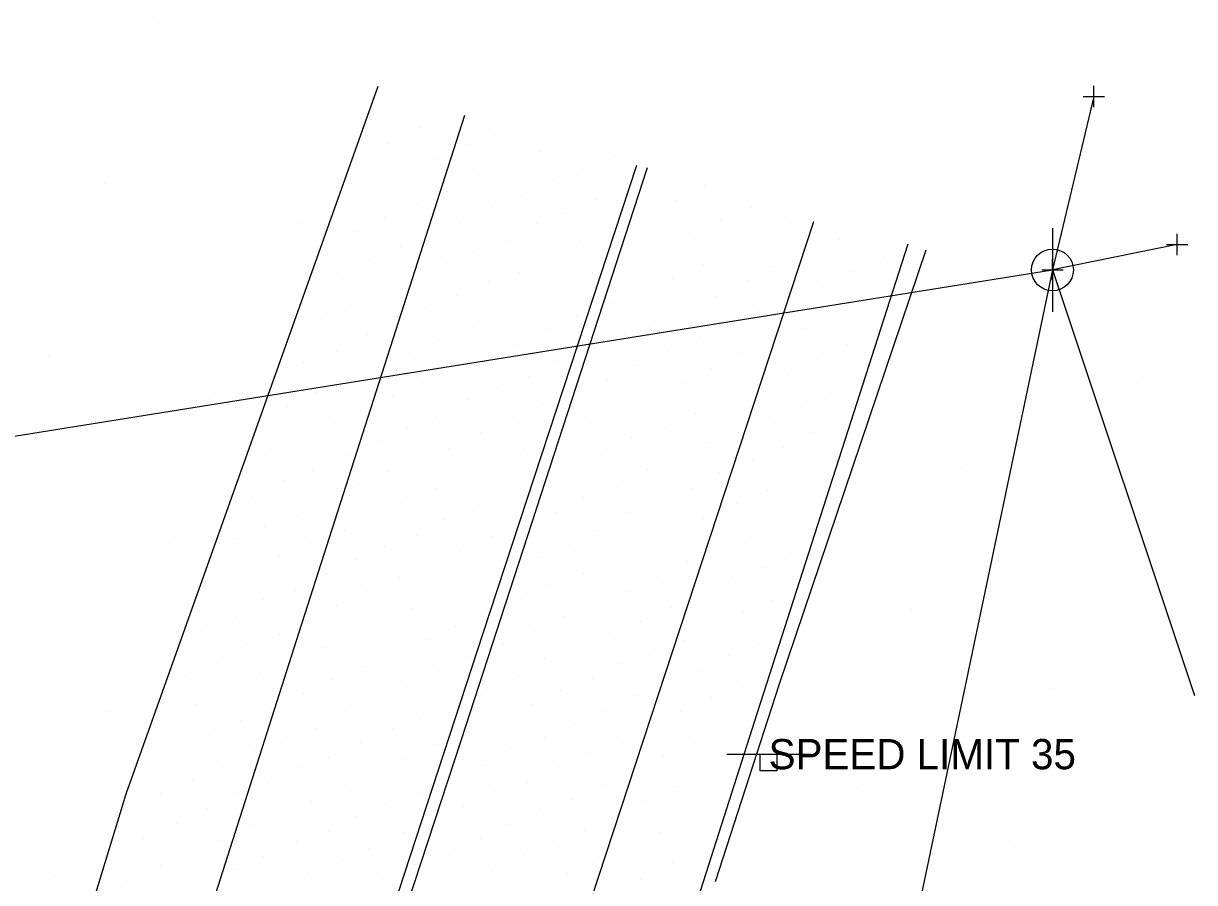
# Model space of a CAD drawing. Extents: x 0 to 1739264, y 0 to 465304.
# Drawn here: x 1739010.3 to 1739080.1, y 465244.9 to 465296.2 of the extents above; entities that cross this region are included whole.
import ezdxf

# ---------------------------------------------------------------- set-up
doc = ezdxf.new("R2010")
doc.units = 0
for name, color, linetype in [('Default', 7, 'Continuous'), ('S_Ground_SpotElevation', 7, 'Continuous'), ('S_Survey_Shot', 7, 'Continuous'), ('S_Terrain_Holes', 7, 'Continuous'), ('S_Terrain_Imported_Contours', 7, 'Continuous'), ('S_Terrain_Triangle_Vertices', 7, 'Continuous'), ('S_Text', 7, 'Continuous'), ('S_Traffic_Sign_SinglePost', 7, 'Continuous'), ('S_Utilities_AG_Communications', 7, 'Continuous'), ('S_Utilities_GuyWire3', 7, 'Continuous'), ('S_Utilities_Pole_Power', 7, 'Continuous')]:
    doc.layers.add(name, color=color, linetype=linetype)

# ---------------------------------------------------------------- blocks, each defined once
blk = doc.blocks.new('POINT_DISPLAY')
at = {"layer": 'Default'}
blk.add_line((0, 0), (0, 0), dxfattribs=at)

msp = doc.modelspace()

# ---------------------------------------------------------------- linework, layer by layer
at = {"layer": 'S_Survey_Shot'}
for p, q in [((1739074.096331, 465291.168485), (1739074.093669, 465292.440915)), ((1739073.458785, 465291.803369), (1739074.731215, 465291.806031)), ((1739074.095, 465291.8047), (1739074.095, 465291.8047)), ((1739079.068331, 465282.334085), (1739079.065669, 465283.606515)), ((1739078.430785, 465282.968969), (1739079.703215, 465282.971631)), ((1739079.067, 465282.9703), (1739079.067, 465282.9703)), ((1739071.634331, 465280.822185), (1739071.631669, 465282.094615)), ((1739071.634331, 465280.822185), (1739071.631669, 465282.094615)), ((1739070.996785, 465281.457069), (1739072.269215, 465281.459731)), ((1739070.996785, 465281.457069), (1739072.269215, 465281.459731)), ((1739071.633, 465281.4584), (1739071.633, 465281.4584)), ((1739071.633, 465281.4584), (1739071.633, 465281.4584))]:
    msp.add_line(p, q, dxfattribs=at)
at = {"layer": 'S_Terrain_Holes'}
for points in [[(1738856.840841, 464753.154236), (1738864.057181, 464775.7454), (1738868.5654, 464789.017493), (1738877.2832, 464816.667503), (1738894.6762, 464871.298499), (1738908.615099, 464914.227276), (1738925.968706, 464967.700787), (1738931.720797, 464985.987408), (1738937.417894, 465002.810894), (1738942.679705, 465019.271282), (1738946.949205, 465031.543377), (1738957.801699, 465065.627422), (1738970.933794, 465105.251873), (1738981.084093, 465138.214092), (1738987.350398, 465160.501376), (1738994.117907, 465180.316815), (1739002.701601, 465206.97459), (1739010.434099, 465230.699413), (1739016.388903, 465250.214703), (1739024.141405, 465271.975903), (1739031.418001, 465292.412487)], [(1739063.0161, 465283.000195), (1739054.024202, 465255.054608), (1739049.4284, 465240.685009), (1739049.815203, 465236.204296), (1739047.1234, 465227.914501), (1739043.67, 465216.427685), (1739042.442102, 465214.161694), (1739040.084001, 465206.821911), (1739030.010698, 465174.744122), (1739023.975405, 465156.789227), (1739021.450701, 465151.395123), (1739017.4265, 465140.617291), (1739011.494493, 465124.187481)]]:
    msp.add_lwpolyline(points, dxfattribs=at)
at = {"layer": 'S_Terrain_Imported_Contours'}
for points in [[(1739036.578798, 465290.667492), (1739026.541399, 465259.332012), (1739013.6942, 465219.063488), (1738999.442797, 465174.850323), (1738985.582293, 465132.024273), (1738970.199999, 465085.108929), (1738952.192003, 465029.358624), (1738937.750505, 464984.645672), (1738924.644899, 464943.318829), (1738905.560399, 464884.157001), (1738885.695701, 464823.240203), (1738863.6675, 464755.019294), (1738861.917132, 464749.554455)], [(1738871.099421, 464743.042961), (1738872.2397, 464746.6146), (1738884.148, 464784.717796), (1738894.996801, 464817.751098), (1738911.848199, 464869.926002), (1738930.302797, 464927.737591), (1738944.359194, 464971.624127), (1738958.087007, 465014.085796), (1738974.263903, 465064.602886), (1738992.370806, 465120.419476), (1739017.617296, 465198.443401), (1739037.679499, 465259.797009), (1739046.847902, 465287.700512)], [(1739047.457499, 465287.543713), (1739036.361299, 465253.386303), (1739023.629793, 465214.581799), (1739012.533693, 465180.659283), (1739000.839403, 465144.457989), (1738988.796495, 465107.402325), (1738973.524599, 465060.372296), (1738959.218599, 465015.277325), (1738946.4993, 464976.09959), (1738932.162996, 464931.360577), (1738918.509, 464889.008399), (1738909.080301, 464859.274802), (1738899.9057, 464830.791198), (1738886.617, 464789.705497), (1738873.9013, 464749.930595), (1738871.579396, 464742.691331)], [(1738880.224773, 464736.284008), (1738881.2288, 464739.449607), (1738893.811099, 464778.771506), (1738907.7459, 464822.0036), (1738924.2609, 464872.5013), (1738939.901598, 464921.282574), (1738960.695803, 464986.497418), (1738980.188906, 465046.965923), (1739002.893496, 465116.574383), (1739021.976305, 465176.353375), (1739041.488497, 465235.866894), (1739057.407396, 465284.356213)]]:
    msp.add_lwpolyline(points, dxfattribs=at)
at = {"layer": 'S_Terrain_Triangle_Vertices'}
msp.add_lwpolyline([(1739051.533602, 465244.994091), (1739055.348597, 465256.783306), (1739064.1029, 465282.664288)], dxfattribs=at)
at = {"layer": 'S_Traffic_Sign_SinglePost'}
msp.add_line((1739052.210924, 465252.5851), (1739057.201076, 465252.5851), dxfattribs=at)
msp.add_lwpolyline([(1739054.206985, 465252.5851), (1739055.205015, 465252.5851), (1739055.205015, 465251.58707), (1739054.206985, 465251.58707)], close=True, dxfattribs=at)
at = {"layer": 'S_Utilities_AG_Communications'}
for p, q in [((1738988.171694, 465268.093792), (1739071.632502, 465281.458386)), ((1739071.632502, 465281.458386), (1739080.108797, 465256.089306))]:
    msp.add_line(p, q, dxfattribs=at)
msp.add_lwpolyline([(1739071.632502, 465281.458386), (1739041.748697, 465139.054608), (1739010.442507, 464998.221295)], dxfattribs=at)
at = {"layer": 'S_Utilities_GuyWire3'}
for points in [[(1739074.095, 465291.8047), (1739071.633, 465281.4584)], [(1739079.067, 465282.9703), (1739071.633, 465281.4584)]]:
    msp.add_lwpolyline(points, dxfattribs=at)
at = {"layer": 'S_Utilities_Pole_Power'}
msp.add_line((1739071.633, 465283.953476), (1739071.633, 465278.963324), dxfattribs=at)
msp.add_circle((1739071.633, 465281.4584), 1.247538, dxfattribs=at)

# ---------------------------------------------------------------- block references
at = {"layer": 'S_Ground_SpotElevation'}
for p in [(1739018.331897, 465296.158886), (1739029.631404, 465292.058697), (1739033.025096, 465291.630669), (1739035.831004, 465290.67205), (1739033.931895, 465289.929375), (1739038.329997, 465289.616508), (1739032.058299, 465288.971733), (1739036.66151, 465288.954643), (1739041.016093, 465288.540947), (1739034.966289, 465288.082451), (1739039.135387, 465287.766411), (1739045.516887, 465288.302299), (1739032.908305, 465287.334038), (1739037.410991, 465287.123833), (1739043.579784, 465287.524956), (1739048.260905, 465287.169731), (1739015.122502, 465286.585491), (1739031.047008, 465286.474663), (1739041.871684, 465286.863335), (1739046.316295, 465286.642143), (1739050.909404, 465286.47979), (1739035.533885, 465286.132866), (1739039.940807, 465285.921318), (1739044.387096, 465285.669243), (1739049.167094, 465285.623344), (1739033.797191, 465285.412163), (1739038.212505, 465285.292656), (1739053.671611, 465285.191093), (1739026.848696, 465284.261303), (1739031.823588, 465284.55645), (1739036.323711, 465284.325249), (1739040.844005, 465284.206474), (1739042.583507, 465284.809135), (1739047.330791, 465284.614189), (1739051.849406, 465284.413628), (1739056.03831, 465284.321098), (1739030.015605, 465283.742607), (1739034.422191, 465283.477348), (1739045.295787, 465283.968559), (1739049.995311, 465283.687553), (1739054.47639, 465283.530815), (1739032.725108, 465282.850151), (1739039.057384, 465283.150566), (1739043.491893, 465283.109428), (1739048.208598, 465282.860649), (1739058.932689, 465283.263603), (1739030.914683, 465282.081474), (1739037.111888, 465282.523003), (1739041.536082, 465282.186455), (1739046.353984, 465282.06768), (1739052.625987, 465282.538628), (1739057.001689, 465282.439751), (1739061.552409, 465282.141899), (1739035.492198, 465281.829155), (1739050.803294, 465281.774223), (1739055.002483, 465281.683037), (1739059.759898, 465281.370415), (1739028.999004, 465281.19915), (1739033.495891, 465281.005669), (1739037.979503, 465280.789238), (1739039.851909, 465281.314384), (1739044.208903, 465281.301933), (1739048.983195, 465280.968925), (1739053.469585, 465280.828544), (1739031.606395, 465280.10894), (1739042.446605, 465280.590874), (1739047.168285, 465280.190849), (1739057.89619, 465280.43914), (1739029.800487, 465279.37896), (1739036.087199, 465279.937797), (1739040.656901, 465279.708916), (1739045.278606, 465279.530571), (1739049.717998, 465279.332451), (1739051.5955, 465279.86663), (1739055.961711, 465279.795708), (1739060.554393, 465279.503593), (1739034.240001, 465279.16375), (1739038.740794, 465278.843193), (1739043.269298, 465278.65435), (1739054.099986, 465279.10125), (1739058.733287, 465278.738823), (1739069.336102, 465279.151196), (1739028.072215, 465278.512749), (1739032.451488, 465278.278618), (1739037.115489, 465278.116142), (1739041.441783, 465277.916923), (1739047.897502, 465278.391533), (1739052.426402, 465278.163261), (1739056.902385, 465277.952934), (1739030.808208, 465277.580742), (1739035.040385, 465277.325127), (1739046.101298, 465277.635795), (1739050.611705, 465277.352714), (1739054.863811, 465277.217216), (1739028.914409, 465276.621635), (1739033.269786, 465276.551689), (1739039.578899, 465276.949394), (1739044.302898, 465276.770439), (1739048.701884, 465276.714653), (1739059.386302, 465277.008842), (1739011.746905, 465276.385601), (1739026.963206, 465275.967338), (1739037.756602, 465276.165947), (1739042.103801, 465275.98748), (1739052.9304, 465276.458794), (1739057.63679, 465276.145805), (1739031.413097, 465275.611381), (1739035.868907, 465275.521538), (1739040.368785, 465275.102592), (1739046.891185, 465275.744194), (1739051.315196, 465275.590996), (1739055.889293, 465275.285454), (1739029.575206, 465274.908134), (1739034.05601, 465274.730522), (1739038.555705, 465274.465874), (1739045.099193, 465274.877983), (1739049.560008, 465274.727836), (1739054.031108, 465274.540947), (1739076.705701, 465274.790814), (1739021.371295, 465273.739086), (1739027.76649, 465274.135307), (1739032.306407, 465273.943535), (1739036.833507, 465273.741875), (1739043.136088, 465274.237846), (1739047.743388, 465273.957207), (1739052.061412, 465273.768486), (1739058.388286, 465274.08477), (1739025.9976, 465273.305961), (1739030.355083, 465273.019829), (1739041.227611, 465273.469047), (1739045.897502, 465272.989921), (1739056.658305, 465273.395805), (1739034.873393, 465272.618339), (1739039.467784, 465272.60186), (1739044.101909, 465272.285576), (1739050.322703, 465272.920341), (1739054.751292, 465272.710503), (1739028.817699, 465272.279838), (1739033.145305, 465271.97686), (1739037.522899, 465271.750908), (1739048.565684, 465272.009453), (1739052.9304, 465271.789848), (1739057.407512, 465271.780083), (1739026.760997, 465271.526298), (1739031.423289, 465271.203667), (1739041.9882, 465271.529961), (1739046.542094, 465271.449638), (1739051.154796, 465271.193046), (1739025.028697, 465270.729545), (1739029.529796, 465270.441337), (1739035.605998, 465270.8377), (1739040.107005, 465270.686455), (1739044.726604, 465270.496757), (1739055.575694, 465270.856987), (1739027.504314, 465269.488579), (1739033.898601, 465270.183403), (1739038.261912, 465269.979423), (1739043.025005, 465269.601738), (1739047.511699, 465269.56353), (1739049.297191, 465270.18267), (1739053.72581, 465270.095268), (1739066.196399, 465269.595592), (1739025.828288, 465268.900566), (1739032.015605, 465269.440239), (1739036.673991, 465269.220634), (1739041.132609, 465268.887138), (1739051.791911, 465269.40374), (1739056.378307, 465269.141533), (1739030.222301, 465268.671562), (1739034.887187, 465268.40081), (1739039.229411, 465268.236626), (1739045.672008, 465268.633842), (1739050.13911, 465268.445976), (1739054.621806, 465268.298759), (1739023.863505, 465267.813774), (1739028.561595, 465267.7929), (1739032.813701, 465267.597465), (1739043.681895, 465267.881523), (1739048.194011, 465267.585136), (1739052.77589, 465267.503715), (1739026.620494, 465266.794975), (1739031.071483, 465266.74395), (1739037.398387, 465267.357963), (1739042.051799, 465267.01226), (1739046.429484, 465266.968681), (1739024.672588, 465266.18206), (1739035.40269, 465266.555839), (1739040.220897, 465266.179863), (1739050.820293, 465266.638359), (1739055.442088, 465266.354423), (1739022.881908, 465265.435478), (1739029.388591, 465265.896049), (1739033.723308, 465265.644585), (1739038.201182, 465265.570854), (1739044.477702, 465265.904961), (1739049.086284, 465265.796806), (1739053.617198, 465265.535087), (1739073.571, 465265.408093), (1739019.005694, 465265.219311), (1739027.365306, 465265.120415), (1739031.809001, 465264.995659), (1739036.294505, 465264.781425), (1739042.823405, 465265.099052), (1739047.256389, 465264.826836), (1739051.681102, 465264.820244), (1739056.022807, 465264.634575), (1739025.531413, 465264.350639), (1739030.063213, 465264.171562), (1739034.410411, 465263.910942), (1739041.005199, 465264.297661), (1739045.356883, 465264.069511), (1739049.889384, 465264.074272), (1739023.970897, 465263.450249), (1739028.360911, 465263.345146), (1739038.819804, 465263.642876), (1739043.645305, 465263.353325), (1739054.345012, 465263.687675), (1739022.027415, 465262.653007), (1739032.67039, 465263.110039), (1739037.174297, 465262.938042), (1739041.617992, 465262.617851), (1739048.099803, 465263.082085), (1739052.491496, 465263.051811), (1739026.506602, 465262.364433), (1739030.726512, 465262.256157), (1739035.281596, 465261.989067), (1739039.985088, 465261.833305), (1739046.230785, 465262.273735), (1739050.658092, 465261.955742), (1739024.555614, 465261.80352), (1739028.909312, 465261.473442), (1739033.448985, 465261.295952), (1739037.8968, 465261.128593), (1739044.349101, 465261.510307), (1739048.904582, 465261.33184), (1739054.941692, 465261.75164), (1739063.2186, 465261.191601), (1739022.88499, 465260.690605), (1739027.078593, 465260.515312), (1739031.53651, 465260.416313), (1739042.535106, 465260.796196), (1739047.072093, 465260.512627), (1739053.223094, 465261.078056), (1739020.910503, 465259.870048), (1739025.545116, 465259.732841), (1739036.030498, 465260.203056), (1739040.767589, 465259.982963), (1739045.232707, 465259.745537), (1739051.509196, 465260.406547), (1739023.586314, 465259.168266), (1739029.69099, 465259.653984), (1739034.276805, 465259.412651), (1739038.916209, 465259.203544), (1739049.685496, 465259.377861), (1739054.080791, 465259.210136), (1739028.095012, 465258.936333), (1739032.429484, 465258.71624), (1739036.862804, 465258.342705), (1739043.4145, 465259.006157), (1739047.886485, 465258.766411), (1739052.311992, 465258.481743), (1739021.856914, 465258.080498), (1739026.090404, 465258.072563), (1739030.493205, 465257.808281), (1739035.017192, 465257.649101), (1739041.332683, 465258.262749), (1739045.908488, 465257.991142), (1739019.957988, 465257.209892), (1739024.349803, 465257.332939), (1739028.693309, 465257.04644), (1739039.768291, 465257.248466), (1739044.224712, 465257.067436), (1739050.527507, 465257.591972), (1739022.349193, 465256.262749), (1739026.944499, 465256.225273), (1739033.113383, 465256.679619), (1739037.861186, 465256.50164), (1739042.303386, 465256.355156), (1739048.701701, 465256.801567), (1739053.165782, 465256.706962), (1739071.487496, 465256.514111), (1739020.537486, 465255.553032), (1739031.555583, 465255.938652), (1739036.090404, 465255.771294), (1739040.567393, 465255.530815), (1739046.693706, 465256.080376), (1739051.271098, 465255.933037), (1739015.423098, 465255.145397), (1739024.985789, 465255.366142), (1739029.482799, 465255.213554), (1739044.981303, 465255.177421), (1739049.464793, 465255.126152), (1739023.194987, 465254.573784), (1739032.288402, 465254.139946), (1739033.935191, 465254.796562), (1739038.684489, 465254.540214), (1739043.139812, 465254.394951), (1739047.605296, 465254.220146), (1739021.367503, 465253.680961), (1739025.960796, 465253.589287), (1739027.722789, 465254.114555), (1739036.833995, 465253.914848), (1739041.350688, 465253.5606), (1739045.696605, 465253.528496), (1739052.113109, 465253.96331), (1739019.545695, 465252.957939), (1739024.06779, 465252.73455), (1739030.353191, 465253.283623), (1739034.752391, 465253.155693), (1739039.325999, 465253.00457), (1739050.289012, 465253.220756), (1739028.450114, 465252.363701), (1739033.030803, 465252.329033), (1739044.000285, 465252.64788), (1739048.437907, 465252.445366), (1739022.118205, 465251.870781), (1739026.691386, 465251.823784), (1739031.128795, 465251.54583), (1739035.748912, 465251.402519), (1739037.615398, 465251.904838), (1739042.166209, 465251.814995), (1739046.53181, 465251.754936), (1739051.115001, 465251.349541), (1739020.333507, 465251.097099), (1739024.807109, 465250.950371), (1739029.466411, 465250.780937), (1739040.314098, 465250.920463), (1739044.803599, 465250.694511), (1739049.254283, 465250.682548), (1739018.4575, 465250.208427), (1739023.025188, 465250.209038), (1739033.811107, 465250.25103), (1739038.332103, 465250.360405), (1739060.029399, 465250.51469), (1739021.244701, 465249.372856), (1739027.44041, 465249.787407), (1739031.863994, 465249.627128), (1739036.512797, 465249.444633), (1739041.101695, 465249.253593), (1739042.954295, 465249.899956), (1739047.363689, 465249.753593), (1739025.782115, 465249.17791), (1739030.048503, 465248.866508), (1739045.641795, 465248.903007), (1739050.093608, 465248.701347), (1739019.402415, 465248.424736), (1739023.800609, 465248.355522), (1739028.4546, 465247.967949), (1739032.948192, 465247.896049), (1739034.752788, 465248.481499), (1739039.279796, 465248.392265), (1739043.71049, 465248.001762), (1739048.283092, 465247.916313), (1739017.450999, 465247.527275), (1739021.928599, 465247.42913), (1739026.546703, 465247.352104), (1739037.501384, 465247.548881), (1739041.881297, 465247.436333), (1739046.323711, 465247.263969), (1739020.153789, 465246.748711), (1739024.592113, 465246.486137), (1739030.872905, 465246.985527), (1739035.64619, 465246.623955), (1739040.103892, 465246.635307), (1739044.537303, 465246.45623), (1739069.386203, 465247.124706), (1739018.411998, 465245.957817), (1739029.288188, 465246.326469), (1739033.596202, 465245.995903), (1739048.988292, 465246.09771), (1739012.1328, 465245.262493), (1739022.849895, 465245.718437), (1739027.189891, 465245.389336), (1739031.651683, 465245.166801), (1739038.224101, 465245.697929), (1739042.725902, 465245.469047), (1739047.040599, 465245.082451), (1739016.419292, 465245.032036)]:
    msp.add_blockref('POINT_DISPLAY', p, dxfattribs=at)

# ---------------------------------------------------------------- texts
at = {"layer": 'S_Text'}
msp.add_text('SPEED LIMIT 35', height=1.8, dxfattribs=at).set_placement((1739054.706, 465251.6851))

doc.saveas('drawing.dxf')
